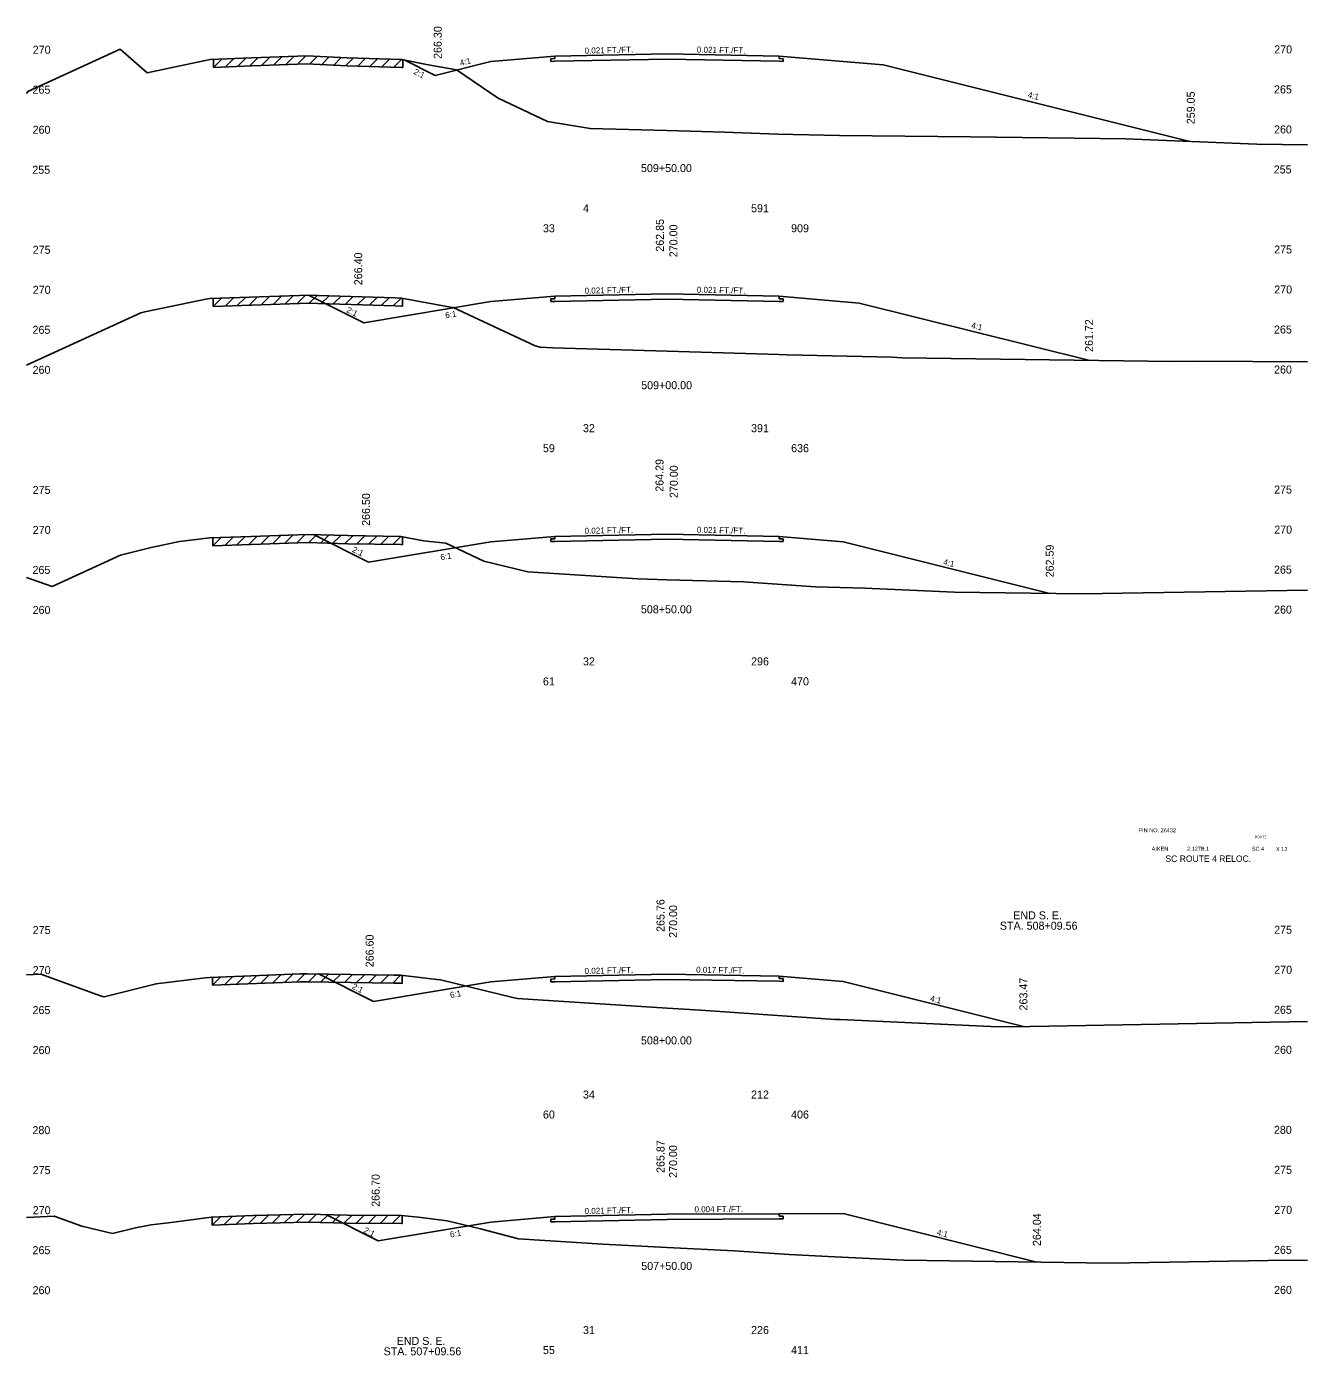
# Model space of a CAD drawing. Extents: x 2967 to 4323, y -3677 to -817.
# Drawn here: x 3188.8 to 3348.8, y -2377.5 to -2211.4 of the extents above; entities that cross this region are included whole.
import ezdxf

# ---------------------------------------------------------------- set-up
doc = ezdxf.new("R2010")
doc.units = 0
for name, color, linetype in [('Level 1', 7, 'Continuous'), ('Level 10', 7, 'Continuous'), ('Level 11', 7, 'Continuous'), ('Level 12', 7, 'Continuous'), ('Level 20', 7, 'Continuous'), ('Level 3', 7, 'Continuous'), ('Level 32', 7, 'Continuous'), ('Level 33', 7, 'Continuous'), ('Level 59', 7, 'Continuous'), ('Level 6', 7, 'Continuous'), ('Level 60', 7, 'Continuous'), ('Level 61', 7, 'Continuous'), ('Level 7', 7, 'Continuous')]:
    doc.layers.add(name, color=color, linetype=linetype)

msp = doc.modelspace()

# ---------------------------------------------------------------- linework, layer by layer
at = {"layer": 'Level 11'}
for p, q in [((3254.76, -2215.43), (3254.26, -2215.44)), ((3254.26, -2215.44), (3254.26, -2215.78)), ((3254.26, -2215.78), (3254.76, -2215.77)), ((3254.76, -2215.13), (3254.76, -2215.43)), ((3282.76, -2215.43), (3282.76, -2215.13)), ((3283.26, -2215.44), (3282.76, -2215.43)), ((3282.76, -2215.77), (3283.26, -2215.78)), ((3283.26, -2215.78), (3283.26, -2215.44)), ((3254.76, -2245.43), (3254.26, -2245.44)), ((3254.26, -2245.44), (3254.26, -2245.78)), ((3254.26, -2245.78), (3254.76, -2245.77)), ((3254.76, -2245.13), (3254.76, -2245.43)), ((3282.76, -2245.43), (3282.76, -2245.13)), ((3283.26, -2245.44), (3282.76, -2245.43)), ((3282.76, -2245.77), (3283.26, -2245.78)), ((3283.26, -2245.78), (3283.26, -2245.44)), ((3254.76, -2275.43), (3254.26, -2275.44)), ((3254.26, -2275.44), (3254.26, -2275.78)), ((3254.26, -2275.78), (3254.76, -2275.77)), ((3254.76, -2275.13), (3254.76, -2275.43)), ((3282.76, -2275.43), (3282.76, -2275.13)), ((3283.26, -2275.44), (3282.76, -2275.43)), ((3282.76, -2275.77), (3283.26, -2275.78)), ((3283.26, -2275.78), (3283.26, -2275.44)), ((3254.76, -2330.43), (3254.26, -2330.44)), ((3254.26, -2330.44), (3254.26, -2330.78)), ((3254.26, -2330.78), (3254.76, -2330.77)), ((3254.76, -2330.13), (3254.76, -2330.43)), ((3282.76, -2330.38), (3282.76, -2330.08)), ((3283.26, -2330.39), (3282.76, -2330.38)), ((3282.76, -2330.72), (3283.26, -2330.73)), ((3283.26, -2330.73), (3283.26, -2330.39)), ((3254.76, -2360.43), (3254.26, -2360.44)), ((3254.26, -2360.44), (3254.26, -2360.78)), ((3254.26, -2360.78), (3254.76, -2360.77)), ((3254.76, -2360.13), (3254.76, -2360.43)), ((3282.76, -2360.08), (3282.76, -2359.78)), ((3283.26, -2360.08), (3282.76, -2360.08)), ((3282.76, -2360.42), (3283.26, -2360.42)), ((3283.26, -2360.42), (3283.26, -2360.08))]:
    msp.add_line(p, q, dxfattribs=at)
at = {"layer": 'Level 12'}
for p, q in [((3268.76, -2215.48), (3254.76, -2215.77)), ((3282.76, -2215.77), (3268.76, -2215.48)), ((3268.76, -2245.48), (3254.76, -2245.77)), ((3282.76, -2245.77), (3268.76, -2245.48)), ((3268.76, -2275.48), (3254.76, -2275.77)), ((3282.76, -2275.77), (3268.76, -2275.48)), ((3268.76, -2330.48), (3254.76, -2330.77)), ((3282.76, -2330.72), (3268.76, -2330.48)), ((3268.76, -2360.48), (3254.76, -2360.77)), ((3282.76, -2360.42), (3268.76, -2360.48))]:
    msp.add_line(p, q, dxfattribs=at)
at = {"layer": 'Level 59'}
for p, q in [((3254.76, -2215.13), (3268.76, -2214.84)), ((3268.76, -2214.84), (3282.76, -2215.13)), ((3254.76, -2245.13), (3268.76, -2244.84)), ((3268.76, -2244.84), (3282.76, -2245.13)), ((3254.76, -2275.13), (3268.76, -2274.84)), ((3268.76, -2274.84), (3282.76, -2275.13)), ((3254.76, -2330.13), (3268.76, -2329.84)), ((3268.76, -2329.84), (3282.76, -2330.08)), ((3254.76, -2360.13), (3268.76, -2359.84)), ((3268.76, -2359.84), (3282.76, -2359.78))]:
    msp.add_line(p, q, dxfattribs=at)
at = {"layer": 'Level 6'}
for p, q in [((3246.76, -2215.8), (3254.76, -2215.13)), ((3282.76, -2215.13), (3295.75, -2216.22)), ((3246.76, -2245.8), (3254.76, -2245.13)), ((3282.76, -2245.13), (3292.76, -2245.97)), ((3246.76, -2275.8), (3254.76, -2275.13)), ((3282.76, -2275.13), (3290.76, -2275.8)), ((3246.76, -2330.8), (3254.76, -2330.13)), ((3282.76, -2330.08), (3290.76, -2330.74)), ((3246.76, -2360.8), (3254.76, -2360.13)), ((3282.76, -2359.78), (3290.76, -2359.75))]:
    msp.add_line(p, q, dxfattribs=at)
at = {"layer": 'Level 60'}
for p, q in [((3188.93, -2219.54), (3200.43, -2214.24)), ((3200.43, -2214.24), (3203.83, -2217.22)), ((3203.83, -2217.22), (3206.95, -2216.54)), ((3206.95, -2216.54), (3211.68, -2215.55)), ((3211.68, -2215.55), (3216.85, -2215.35)), ((3216.85, -2215.35), (3223.77, -2215.1)), ((3223.77, -2215.1), (3228.82, -2215.32)), ((3228.82, -2215.32), (3235.62, -2215.54)), ((3235.62, -2215.54), (3238.73, -2216.16)), ((3238.73, -2216.16), (3242.46, -2216.85)), ((3242.46, -2216.85), (3247.68, -2220.38)), ((3188.76, -2219.77), (3188.93, -2219.54)), ((3247.68, -2220.38), (3253.84, -2223.29)), ((3253.84, -2223.29), (3259.15, -2224.15)), ((3259.15, -2224.15), (3268.76, -2224.42)), ((3268.76, -2224.42), (3275.96, -2224.63)), ((3275.96, -2224.63), (3282.59, -2224.88)), ((3282.59, -2224.88), (3290.31, -2225.04)), ((3290.31, -2225.04), (3306.67, -2225.19)), ((3306.67, -2225.19), (3326.06, -2225.47)), ((3326.06, -2225.47), (3342.42, -2226.14)), ((3342.42, -2226.14), (3348.76, -2226.19)), ((3203.52, -2247.07), (3211.17, -2245.48)), ((3211.17, -2245.48), (3211.65, -2245.42)), ((3211.65, -2245.42), (3222.87, -2245.02)), ((3222.87, -2245.02), (3223.76, -2244.99)), ((3223.76, -2244.99), (3234.8, -2245.34)), ((3234.8, -2245.34), (3235.61, -2245.35)), ((3235.61, -2245.35), (3241.72, -2246.48)), ((3241.72, -2246.48), (3242.06, -2246.52)), ((3242.06, -2246.52), (3252.29, -2251.34)), ((3188.76, -2253.75), (3203.02, -2247.19)), ((3203.02, -2247.19), (3203.52, -2247.07)), ((3252.29, -2251.34), (3252.9, -2251.49)), ((3252.9, -2251.49), (3254.45, -2251.59)), ((3254.45, -2251.59), (3268.76, -2252)), ((3268.76, -2252), (3282.75, -2252.39)), ((3282.75, -2252.39), (3283.75, -2252.46)), ((3283.75, -2252.46), (3296.88, -2252.75)), ((3296.88, -2252.75), (3298.12, -2252.8)), ((3298.12, -2252.8), (3331.9, -2253.27)), ((3331.9, -2253.27), (3335.09, -2253.22)), ((3335.09, -2253.22), (3348.76, -2253.33)), ((3204.33, -2276.5), (3207.85, -2275.77)), ((3207.85, -2275.77), (3211.64, -2275.32)), ((3211.64, -2275.32), (3216.81, -2275.13)), ((3216.81, -2275.13), (3223.79, -2274.88)), ((3223.79, -2274.88), (3228.88, -2275.04)), ((3228.88, -2275.04), (3235.53, -2275.15)), ((3235.53, -2275.15), (3238.36, -2275.67)), ((3238.36, -2275.67), (3241.14, -2275.99)), ((3241.14, -2275.99), (3245.87, -2278.22)), ((3191.94, -2281.4), (3200.49, -2277.47)), ((3200.49, -2277.47), (3204.33, -2276.5)), ((3245.87, -2278.22), (3251.38, -2279.56)), ((3251.38, -2279.56), (3265.13, -2280.45)), ((3188.76, -2280.27), (3191.94, -2281.4)), ((3265.13, -2280.45), (3268.76, -2280.55)), ((3268.76, -2280.55), (3278.33, -2280.82)), ((3278.33, -2280.82), (3287.32, -2281.45)), ((3287.32, -2281.45), (3293.46, -2281.58)), ((3293.46, -2281.58), (3304.67, -2282.09)), ((3304.67, -2282.09), (3320.53, -2282.31)), ((3320.53, -2282.31), (3348.76, -2281.83)), ((3188.76, -2329.92), (3190.55, -2329.84)), ((3190.55, -2329.84), (3197.99, -2332.54)), ((3198.47, -2332.65), (3204.94, -2331.04)), ((3204.94, -2331.04), (3211.06, -2330.3)), ((3211.06, -2330.3), (3211.65, -2330.23)), ((3211.65, -2330.23), (3222.97, -2329.81)), ((3222.97, -2329.81), (3223.81, -2329.79)), ((3223.81, -2329.79), (3234.64, -2329.97)), ((3234.64, -2329.97), (3235.48, -2329.97)), ((3235.48, -2329.97), (3240.02, -2330.49)), ((3240.02, -2330.49), (3240.46, -2330.55)), ((3240.46, -2330.55), (3249.52, -2332.74)), ((3197.99, -2332.54), (3198.47, -2332.65)), ((3249.52, -2332.74), (3250.07, -2332.88)), ((3250.07, -2332.88), (3268.76, -2334.08)), ((3268.76, -2334.08), (3272.93, -2334.35)), ((3272.93, -2334.35), (3274.76, -2334.45)), ((3274.76, -2334.45), (3289.77, -2335.48)), ((3289.77, -2335.48), (3290.38, -2335.51)), ((3290.38, -2335.51), (3309.22, -2336.36)), ((3311.85, -2336.4), (3348.76, -2335.76)), ((3309.22, -2336.36), (3311.85, -2336.4)), ((3188.76, -2360.22), (3192.22, -2360.07)), ((3192.22, -2360.07), (3195.65, -2361.31)), ((3204.32, -2361.15), (3207.15, -2360.81)), ((3207.15, -2360.81), (3211.82, -2360.19)), ((3211.82, -2360.19), (3217.05, -2360)), ((3217.05, -2360), (3223.82, -2359.84)), ((3223.82, -2359.84), (3228.82, -2359.93)), ((3228.82, -2359.93), (3235.59, -2359.97)), ((3235.59, -2359.97), (3237.68, -2360.21)), ((3237.68, -2360.21), (3241.28, -2360.66)), ((3241.28, -2360.66), (3245.45, -2361.67)), ((3195.65, -2361.31), (3199.51, -2362.24)), ((3199.51, -2362.24), (3202.37, -2361.52)), ((3202.37, -2361.52), (3204.32, -2361.15)), ((3245.45, -2361.67), (3250.22, -2362.89)), ((3250.22, -2362.89), (3260.74, -2363.56)), ((3260.74, -2363.56), (3268.76, -2363.97)), ((3268.76, -2363.97), (3277.15, -2364.4)), ((3277.15, -2364.4), (3284.03, -2364.87)), ((3284.03, -2364.87), (3289.72, -2365.16)), ((3289.72, -2365.16), (3298.34, -2365.55)), ((3298.34, -2365.55), (3324.04, -2365.94)), ((3324.04, -2365.94), (3346.35, -2365.56)), ((3346.35, -2365.56), (3348.76, -2365.59))]:
    msp.add_line(p, q, dxfattribs=at)
at = {"layer": 'Level 61'}
for p, q in [((3213.16, -2215.49), (3212.12, -2216.53)), ((3212.12, -2215.53), (3212.12, -2216.53)), ((3212.12, -2216.53), (3216.85, -2216.35)), ((3214.66, -2215.43), (3213.62, -2216.47)), ((3216.16, -2215.37), (3215.12, -2216.41)), ((3217.65, -2215.32), (3216.62, -2216.36)), ((3216.85, -2216.35), (3223.77, -2216.1)), ((3219.15, -2215.26), (3218.12, -2216.3)), ((3220.65, -2215.21), (3219.62, -2216.25)), ((3222.15, -2215.16), (3221.12, -2216.19)), ((3223.65, -2215.1), (3222.62, -2216.14)), ((3223.77, -2216.1), (3228.82, -2216.32)), ((3225.07, -2215.16), (3224.12, -2216.12)), ((3226.57, -2215.22), (3225.62, -2216.18)), ((3228.07, -2215.29), (3227.12, -2216.25)), ((3229.58, -2215.35), (3228.62, -2216.31)), ((3228.82, -2216.32), (3235.62, -2216.54)), ((3231.08, -2215.39), (3230.12, -2216.36)), ((3232.58, -2215.44), (3231.62, -2216.41)), ((3234.08, -2215.49), (3233.12, -2216.46)), ((3235.58, -2215.54), (3234.62, -2216.51)), ((3235.62, -2216.54), (3235.74, -2216.57)), ((3235.74, -2216.57), (3235.74, -2215.57)), ((3213.11, -2245.37), (3212.07, -2246.4)), ((3212.07, -2245.4), (3212.07, -2246.4)), ((3212.07, -2246.4), (3222.87, -2246.02)), ((3214.61, -2245.31), (3213.57, -2246.35)), ((3216.11, -2245.26), (3215.07, -2246.3)), ((3217.61, -2245.21), (3216.57, -2246.24)), ((3219.11, -2245.15), (3218.07, -2246.19)), ((3220.61, -2245.1), (3219.57, -2246.14)), ((3222.11, -2245.05), (3221.07, -2246.08)), ((3223.61, -2244.99), (3222.57, -2246.03)), ((3222.87, -2246.02), (3223.76, -2245.99)), ((3223.76, -2245.99), (3234.8, -2246.34)), ((3225.04, -2245.03), (3224.07, -2246)), ((3226.54, -2245.07), (3225.57, -2246.04)), ((3228.04, -2245.12), (3227.07, -2246.09)), ((3229.54, -2245.17), (3228.57, -2246.14)), ((3231.04, -2245.22), (3230.07, -2246.19)), ((3232.54, -2245.27), (3231.57, -2246.24)), ((3234.04, -2245.32), (3233.07, -2246.28)), ((3235.55, -2245.35), (3234.57, -2246.33)), ((3234.8, -2246.34), (3235.61, -2246.35)), ((3235.61, -2246.35), (3235.72, -2246.37)), ((3235.72, -2246.37), (3235.72, -2245.37)), ((3213.07, -2275.27), (3212.03, -2276.3)), ((3212.03, -2275.3), (3212.03, -2276.3)), ((3212.03, -2276.3), (3216.81, -2276.13)), ((3214.57, -2275.21), (3213.53, -2276.25)), ((3216.07, -2275.16), (3215.03, -2276.2)), ((3217.57, -2275.11), (3216.53, -2276.14)), ((3216.81, -2276.13), (3223.79, -2275.88)), ((3219.07, -2275.05), (3218.03, -2276.09)), ((3220.57, -2274.99), (3219.53, -2276.03)), ((3222.07, -2274.94), (3221.03, -2275.98)), ((3223.57, -2274.88), (3222.53, -2275.92)), ((3223.79, -2275.88), (3228.88, -2276.04)), ((3225, -2274.91), (3224.03, -2275.88)), ((3226.5, -2274.96), (3225.53, -2275.93)), ((3228, -2275.01), (3227.03, -2275.98)), ((3229.51, -2275.05), (3228.53, -2276.03)), ((3228.88, -2276.04), (3235.53, -2276.15)), ((3231.02, -2275.07), (3230.03, -2276.06)), ((3232.52, -2275.1), (3231.53, -2276.08)), ((3234.02, -2275.12), (3233.03, -2276.11)), ((3235.52, -2275.15), (3234.53, -2276.13)), ((3235.53, -2276.15), (3235.71, -2276.18)), ((3235.71, -2276.18), (3235.71, -2275.18)), ((3213.03, -2330.18), (3211.99, -2331.21)), ((3211.99, -2330.21), (3211.99, -2331.21)), ((3211.99, -2331.21), (3222.97, -2330.81)), ((3214.53, -2330.12), (3213.49, -2331.16)), ((3216.03, -2330.06), (3214.99, -2331.1)), ((3217.53, -2330.01), (3216.49, -2331.05)), ((3219.03, -2329.95), (3217.99, -2330.99)), ((3220.53, -2329.9), (3219.49, -2330.94)), ((3222.03, -2329.84), (3220.99, -2330.88)), ((3223.52, -2329.8), (3222.49, -2330.83)), ((3222.97, -2330.81), (3223.81, -2330.79)), ((3223.81, -2330.79), (3234.64, -2330.97)), ((3224.97, -2329.81), (3223.99, -2330.79)), ((3226.47, -2329.83), (3225.49, -2330.82)), ((3227.97, -2329.86), (3226.99, -2330.84)), ((3229.47, -2329.88), (3228.49, -2330.87)), ((3230.97, -2329.91), (3229.99, -2330.89)), ((3232.47, -2329.93), (3231.49, -2330.91)), ((3233.97, -2329.96), (3232.99, -2330.94)), ((3235.48, -2329.97), (3234.49, -2330.96)), ((3234.64, -2330.97), (3235.48, -2330.97)), ((3235.48, -2330.97), (3235.69, -2331)), ((3235.69, -2331), (3235.69, -2330)), ((3212.99, -2360.15), (3211.95, -2361.19)), ((3211.95, -2360.19), (3211.95, -2361.19)), ((3211.95, -2361.19), (3217.05, -2361)), ((3214.49, -2360.09), (3213.45, -2361.13)), ((3215.99, -2360.04), (3214.95, -2361.08)), ((3217.48, -2359.99), (3216.45, -2361.02)), ((3217.05, -2361), (3223.82, -2360.84)), ((3218.97, -2359.96), (3217.95, -2360.98)), ((3220.47, -2359.92), (3219.45, -2360.94)), ((3221.97, -2359.89), (3220.95, -2360.91)), ((3223.47, -2359.85), (3222.45, -2360.88)), ((3223.82, -2360.84), (3228.82, -2360.93)), ((3224.93, -2359.86), (3223.95, -2360.85)), ((3226.43, -2359.89), (3225.45, -2360.87)), ((3227.93, -2359.91), (3226.95, -2360.9)), ((3229.44, -2359.93), (3228.45, -2360.92)), ((3228.82, -2360.93), (3235.59, -2360.97)), ((3230.94, -2359.94), (3229.95, -2360.93)), ((3232.44, -2359.95), (3231.45, -2360.94)), ((3233.94, -2359.96), (3232.95, -2360.95)), ((3235.44, -2359.97), (3234.45, -2360.96)), ((3235.59, -2360.97), (3235.67, -2360.98)), ((3235.67, -2360.98), (3235.67, -2359.98))]:
    msp.add_line(p, q, dxfattribs=at)
at = {"layer": 'Level 7'}
for p, q in [((3235.91, -2215.6), (3239.79, -2217.54)), ((3246.76, -2215.8), (3239.79, -2217.54)), ((3295.75, -2216.22), (3334.07, -2225.8)), ((3223.97, -2244.99), (3230.88, -2248.45)), ((3230.88, -2248.45), (3246.76, -2245.8)), ((3292.76, -2245.97), (3321.4, -2253.13)), ((3224.59, -2274.9), (3231.48, -2278.35)), ((3231.48, -2278.35), (3246.76, -2275.8)), ((3290.76, -2275.8), (3316.57, -2282.25)), ((3225.21, -2329.81), (3232.08, -2333.25)), ((3232.08, -2333.25), (3246.76, -2330.8)), ((3290.76, -2330.74), (3313.28, -2336.37)), ((3226.15, -2359.88), (3232.68, -2363.15)), ((3232.68, -2363.15), (3246.76, -2360.8)), ((3290.76, -2359.75), (3314.96, -2365.8))]:
    msp.add_line(p, q, dxfattribs=at)

# ---------------------------------------------------------------- texts
at = {"layer": 'Level 1'}
for s, p in [('4', (3258.26, -2234.63)), ('591', (3279.26, -2234.63)), ('33', (3253.26, -2237.13)), ('909', (3284.26, -2237.13)), ('32', (3258.26, -2262.11)), ('391', (3279.26, -2262.11)), ('59', (3253.26, -2264.61)), ('636', (3284.26, -2264.61)), ('32', (3258.26, -2291.25)), ('296', (3279.26, -2291.25)), ('61', (3253.26, -2293.75)), ('470', (3284.26, -2293.75)), ('END S. E.', (3312.01, -2322.98)), ('STA. 508+09.56', (3310.34, -2324.28)), ('34', (3258.26, -2345.37)), ('212', (3279.26, -2345.37)), ('60', (3253.26, -2347.87)), ('406', (3284.26, -2347.87)), ('31', (3258.26, -2374.8)), ('226', (3279.26, -2374.8)), ('END S. E.', (3234.99, -2376.16)), ('STA. 507+09.56', (3233.36, -2377.46)), ('55', (3253.26, -2377.3)), ('411', (3284.26, -2377.3))]:
    msp.add_text(s, height=1, dxfattribs=at).set_placement(p)
at = {"layer": 'Level 10'}
for s, p in [('509+50.00', (3265.51, -2229.61)), ('509+00.00', (3265.53, -2256.74)), ('508+50.00', (3265.5, -2284.74)), ('508+00.00', (3265.51, -2338.61)), ('507+50.00', (3265.54, -2366.79))]:
    msp.add_text(s, height=1, dxfattribs=at).set_placement(p)
for s, p in [('262.85', (3268.37, -2239.56)), ('264.29', (3268.32, -2269.55)), ('265.76', (3268.45, -2324.55)), ('265.87', (3268.45, -2354.67))]:
    msp.add_text(s, height=1, rotation=90, dxfattribs=at).set_placement(p)
at = {"layer": 'Level 20'}
for s, height, p in [('PIN NO. 26432', 0.5, (3327.65, -2312.1)), ('ROUTE', 0.3, (3342.19, -2312.84)), ('AIKEN', 0.5, (3329.31, -2314.41)), (' 2.127B.1', 0.5, (3333.53, -2314.41)), ('SC 4', 0.5, (3341.82, -2314.41)), ('X 12', 0.5, (3344.83, -2314.46)), ('SC ROUTE 4 RELOC.', 0.8, (3331.02, -2315.8))]:
    msp.add_text(s, height=height, dxfattribs=at).set_placement(p)
at = {"layer": 'Level 3'}
for s, p in [(' 270', (3189.16, -2214.82)), (' 270', (3344.24, -2214.78)), (' 265', (3189.13, -2219.82)), (' 265', (3344.21, -2219.78)), (' 260', (3189.14, -2224.82)), (' 260', (3344.22, -2224.78)), (' 255', (3189.1, -2229.82)), (' 255', (3344.18, -2229.78)), (' 275', (3189.15, -2239.82)), (' 275', (3344.23, -2239.78)), (' 270', (3189.16, -2244.82)), (' 270', (3344.24, -2244.78)), (' 265', (3189.13, -2249.82)), (' 265', (3344.21, -2249.78)), (' 260', (3189.14, -2254.82)), (' 260', (3344.22, -2254.78)), (' 275', (3189.15, -2269.82)), (' 275', (3344.23, -2269.78)), (' 270', (3189.16, -2274.82)), (' 270', (3344.24, -2274.78)), (' 265', (3189.13, -2279.82)), (' 265', (3344.21, -2279.78)), (' 260', (3189.14, -2284.82)), (' 260', (3344.22, -2284.78)), (' 275', (3189.15, -2324.82)), (' 275', (3344.23, -2324.78)), (' 270', (3189.16, -2329.82)), (' 270', (3344.24, -2329.78)), (' 265', (3189.13, -2334.82)), (' 265', (3344.21, -2334.78)), (' 260', (3189.14, -2339.82)), (' 260', (3344.22, -2339.78)), (' 280', (3189.12, -2349.82)), (' 280', (3344.2, -2349.78)), (' 275', (3189.15, -2354.82)), (' 275', (3344.23, -2354.78)), (' 270', (3189.16, -2359.82)), (' 270', (3344.24, -2359.78)), (' 265', (3189.13, -2364.82)), (' 265', (3344.21, -2364.78)), (' 260', (3189.14, -2369.82)), (' 260', (3344.22, -2369.78))]:
    msp.add_text(s, height=1, dxfattribs=at).set_placement(p)
at = {"layer": 'Level 32'}
for s, rotation, p in [('0.021 FT./FT.', 1.1916, (3258.47, -2214.81)), ('0.021 FT./FT.', 358.8084, (3272.48, -2214.67)), ('4:1', 14.0362, (3242.98, -2216.35)), ('2:1', 333.435, (3237.03, -2217.32)), ('4:1', 345.9638, (3313.77, -2220.27)), ('0.021 FT./FT.', 1.1916, (3258.47, -2244.81)), ('0.021 FT./FT.', 358.8084, (3272.48, -2244.67)), ('2:1', 333.435, (3228.64, -2247.08)), ('6:1', 9.4623, (3241.12, -2247.89)), ('4:1', 345.9638, (3306.71, -2249.08)), ('0.021 FT./FT.', 1.1916, (3258.47, -2274.81)), ('0.021 FT./FT.', 358.8084, (3272.48, -2274.67)), ('2:1', 333.435, (3229.36, -2277.03)), ('6:1', 9.4623, (3240.52, -2278.12)), ('4:1', 345.9638, (3303.21, -2278.65)), ('0.021 FT./FT.', 1.1916, (3258.47, -2329.81)), ('0.017 FT./FT.', 359.0371, (3272.39, -2329.65)), ('2:1', 333.435, (3229.34, -2331.61)), ('6:1', 9.4623, (3241.72, -2332.82)), ('4:1', 345.9638, (3301.57, -2333.19)), ('0.021 FT./FT.', 1.1916, (3258.47, -2359.81)), ('0.004 FT./FT.', 0.2332, (3272.19, -2359.58)), ('2:1', 333.435, (3230.78, -2362.07)), ('6:1', 9.4623, (3241.72, -2362.74)), ('4:1', 345.9638, (3302.4, -2362.41))]:
    msp.add_text(s, height=0.75, rotation=rotation, dxfattribs=at).set_placement(p)
at = {"layer": 'Level 33'}
for s, p in [('266.30', (3240.62, -2215.47)), ('259.05', (3334.69, -2223.63)), ('266.40', (3230.69, -2243.75)), ('261.72', (3321.98, -2252.08)), ('266.50', (3231.66, -2273.82)), ('262.59', (3317.07, -2280.25)), ('266.60', (3232.11, -2328.97)), ('263.47', (3313.78, -2334.37)), ('266.70', (3232.86, -2358.9)), ('264.04', (3315.46, -2363.8))]:
    msp.add_text(s, height=1, rotation=90, dxfattribs=at).set_placement(p)
at = {"layer": 'Level 59'}
for p in [(3270.06, -2240.62), (3270.11, -2270.71), (3270.02, -2325.66), (3270.02, -2355.66)]:
    msp.add_text(' 270.00', height=1, rotation=90, dxfattribs=at).set_placement(p)

doc.saveas('drawing.dxf')
